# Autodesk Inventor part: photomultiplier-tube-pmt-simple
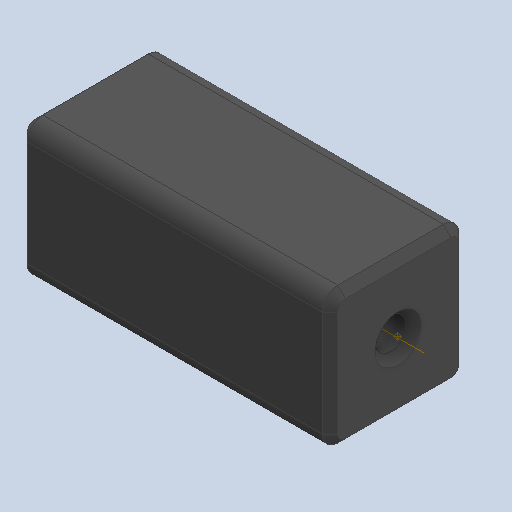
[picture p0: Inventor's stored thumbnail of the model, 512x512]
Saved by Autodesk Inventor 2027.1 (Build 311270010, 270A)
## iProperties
Created: 2026-07
Part Number: photomultiplier-tube-pmt-simple
Material: Generic
Document SubType Name: Modeling
Designer: dunge
Density: 1 g/cm^3
Appearance: Default
Author: dunge
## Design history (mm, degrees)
sketch "Sketch1"
  geometry: L1 (56.642, 13.97)-(56.642, 14.097); L2 (56.642, 14.097)-(64.262, 14.097); L3 (64.262, 14.097)-(64.262, 13.97); L4 (64.262, 13.97)-(63.5, 5.334); L5 (63.5, 5.334)-(63.5, 4.572); L6 (63.5, 4.572)-(63.246, 4.572); L7 (63.246, 4.572)-(63.246, 3.81); L8 (63.246, 3.81)-(2.54, 3.81); L9 (2.54, 3.81)-(2.54, 0); L10 (2.54, 0)-(0, 0); L11 (0, 0)-(0, 13.97); L12 (0, 13.97)-(56.642, 13.97); 1 further point
  constraints: 24 end point, 8 perpendicular, 1 coincident, 1 horizontal, 1 horizontal alignment, 1 parallel, 1 vertical
  dimensions: "d0" = 2.54 distance of L9.end L10.end; "d1" = 13.97 distance of L10.end L11.end; "d2" = 63.5 distance between parallel lines of L5 L11; "d3" = 0.254 distance between parallel lines of L5 L7; "d4" = 0.762 distance of L4.end L5.end; "d6" = 0.127 distance of L2.end L3.end; "d8" = 7.62 distance between parallel lines of L3 L1; "d9" = 3.81 distance of L8.end L9.end; "d10" = 0.762 distance of L6.end L7.end; "d12" = 0.762 distance between parallel lines of L5 L3
revolve "Revolution1" sketch "Sketch1" stored, may be unused: angle "d11" = 360 deg
workpoint "Work Point1"
  workaxis "Work Axis1"
chamfer "Chamfer1" distance "d13" = 1.27; stored, may be unused: second distance "d14" = 3.175, angle "d15" = 45 deg
sketch "Sketch2"
  geometry: L1 (-13.97, 13.97)-(13.97, 13.97); L2 (13.97, 13.97)-(13.97, -13.97); L3 (13.97, -13.97)-(-13.97, -13.97); L4 (-13.97, -13.97)-(-13.97, 13.97); L5 (-13.97, 13.97)-(13.97, -13.97); L6 (13.97, 13.97)-(-13.97, -13.97); 1 further point
  constraints: 12 end point, 2 midpoint, 2 parallel, 2 perpendicular, 1 horizontal
  dimensions: "d16" = 27.94 distance of L1.end L2.end
extrude "Extrusion1" new body sketch "Sketch2" distance "d17" = 63.5; taper "d18" = 0 deg
fillet "Fillet1" dims "d19" = 3.175
sketch "Sketch3"
  geometry: C1 r 3.175 at (0, 0); 1 further point
  constraints: 1 centre point, 1 coincident
  dimensions: "d23" = 6.35 diameter of C1
extrude "Extrusion2" cut sketch "Sketch3" distance "d24" = 50.8; taper "d25" = 0 deg
chamfer "Chamfer2" distance "d20" = 1.5875; stored, may be unused: second distance "d21" = 3.175, angle "d22" = 45 deg
body "Solid1"
node "Finishes"
body "Solid2"
node "Finish2" dims "Finish2_Area" = 829.05454
node "Finish3" dims "Finish3_Area" = 908.84721
